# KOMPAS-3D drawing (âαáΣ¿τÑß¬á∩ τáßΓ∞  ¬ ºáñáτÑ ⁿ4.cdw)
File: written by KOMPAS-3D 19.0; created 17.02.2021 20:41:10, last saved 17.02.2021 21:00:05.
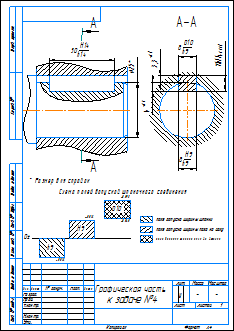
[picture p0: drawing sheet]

Sheet 1: A4, portrait

Document properties: Автор: Юрий

Title block, sheet 1: Наименование: Графическая часть / к задаче №4; Количество листов документа: 1; Форматы листов документа: A4; Литера: у; stored path: C:\Users\Юрий\Desktop\метрология сироп\Графическая часть  к задаче №4.cdw

Views: Вид 1, Вид 2, Разрез А-А
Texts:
  * Размер для справок
  Схема полей допусков шпоночного соединения
  поле допуска ширины шпонки
  поле допуска ширины паза на валу
  поле допуска ширины паза во втулке
Dimensions and other numbers on the sheet: 50; 25; 8; 7; 4; 3,3; -0,036; +0,036; +0,098; +0,040; 1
